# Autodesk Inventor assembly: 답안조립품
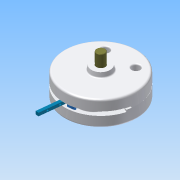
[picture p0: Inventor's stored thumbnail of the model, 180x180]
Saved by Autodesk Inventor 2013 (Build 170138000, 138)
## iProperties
Created: 2015-06
Part Number: 답안조립품
Document SubType Name: Assembly
Designer: Administrator
Author: Administrator
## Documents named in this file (10)
- C:\Documents and Settings\Administrator\바탕 화면\450631V1023\답안조립품.iam
- C:\Documents and Settings\Administrator\바탕 화면\450631V1023\1-본체.ipt
- C:\Documents and Settings\Administrator\바탕 화면\450631V1023\베어링62_22.ipt
- C:\Documents and Settings\Administrator\바탕 화면\450631V1023\덮개.ipt
- C:\Documents and Settings\Administrator\바탕 화면\450631V1023\축.ipt
- C:\Documents and Settings\Administrator\바탕 화면\450631V1023\멈춤링.ipt
- C:\Documents and Settings\Administrator\바탕 화면\450631V1023\슬라이더2.ipt
- C:\Documents and Settings\Administrator\바탕 화면\450631V1023\슬라이더.ipt
- C:\Documents and Settings\Administrator\바탕 화면\450631V1023\평행핀.ipt
- C:\Documents and Settings\Administrator\바탕 화면\450631V1023\M10x35.ipt
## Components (9 placed, 5 different names)
1. 1-본체:1
2. KS B 2023 62/22 - 22 x 50 x 14:1
3. KS B 2023 62/22 - 22 x 50 x 14:2
4. KS B 1320 B B 5 x  20:1
5. KS B 1336 22 x 1.2:1
6. KS B 1336 22 x 1.2:2
7. KS B 2023 62/22 - 22 x 50 x 14:3
8. KS B 1003 - 미터 M 10 x 35:1
9. KS B 1003 - 미터 M 10 x 35:2
